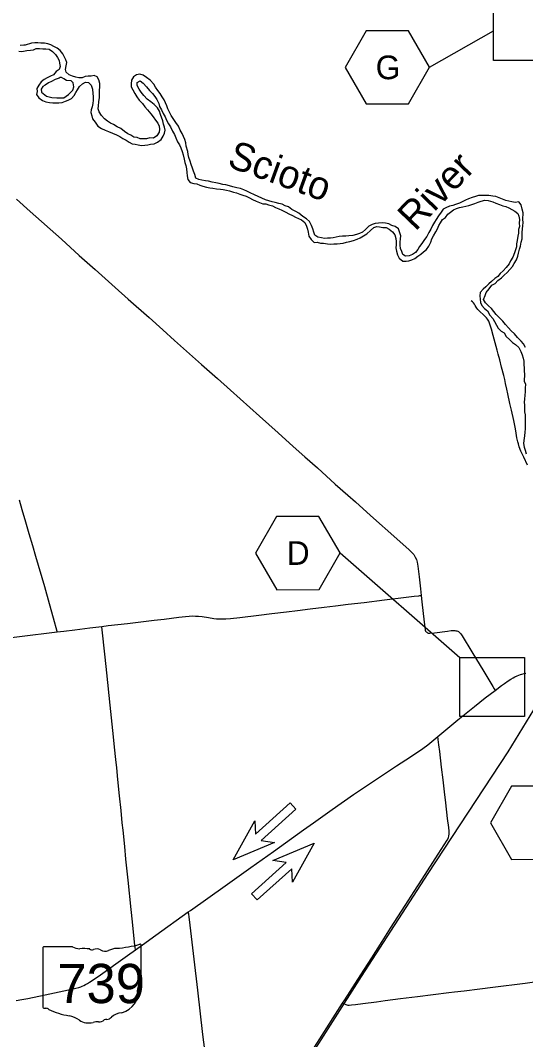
# Model space of a CAD drawing. Extents: x 0 to 680, y 0 to 440.
# Drawn here: x 332.1 to 391.8, y 219.2 to 339.7 of the extents above; entities that cross this region are included whole.
import ezdxf

# ---------------------------------------------------------------- set-up
doc = ezdxf.new("R2010")
doc.units = 0
for name, color, linetype in [('GM_X_County_Road', 7, 'Continuous'), ('GM_X_Major_River', 7, 'Continuous'), ('GM_X_Major_River_Text', 7, 'Continuous'), ('GM_X_State_Location', 7, 'Continuous'), ('GM_X_State_Route', 7, 'Continuous'), ('GM_X_State_Shield', 7, 'Continuous'), ('GM_X_Township_Road', 7, 'Continuous'), ('PM_P_Cells', 7, 'Continuous'), ('RD_X_RR_2', 7, 'Continuous'), ('SH_Border', 7, 'Continuous')]:
    doc.layers.add(name, color=color, linetype=linetype)

msp = doc.modelspace()

# ---------------------------------------------------------------- linework, layer by layer
at = {"layer": 'GM_X_County_Road'}
for points in [[(331.6, 318.59), (333.23, 317.12), (336.91, 313.84), (339.03, 311.94), (340.9, 310.27), (343.26, 308.15), (344.81, 306.76), (347.27, 304.58), (348.89, 303.12), (350.29, 301.89), (353.46, 299.04), (355.35, 297.37), (356.89, 295.98), (360.31, 292.91), (362.52, 290.95), (364.31, 289.34), (365.69, 288.1), (367.16, 286.79), (369.27, 284.89), (370.75, 283.58), (371.65, 282.79), (373.44, 281.18), (376.55, 278.42), (378.02, 277.11), (378.33, 276.8), (378.54, 276.54), (378.73, 276.25), (378.87, 275.95), (378.96, 275.64), (379.03, 275.17), (379.18, 273.9), (379.34, 272.49), (379.43, 271.7)], [(341.7, 268.05), (342.43, 268.14), (344.72, 268.41), (347.87, 268.79), (349.06, 268.92), (350.8, 269.15), (351.56, 269.24), (352, 269.27), (352.44, 269.29), (352.77, 269.28), (353.1, 269.26), (353.53, 269.21), (354.29, 269.1), (354.94, 268.99), (355.26, 268.95), (355.59, 268.93), (355.92, 268.93), (356.35, 268.94), (356.9, 268.98), (357.98, 269.11), (360.26, 269.39), (361.78, 269.58), (363.5, 269.78), (364.8, 269.94), (366.31, 270.12), (367.95, 270.32), (369.31, 270.48), (370.8, 270.67), (372.68, 270.89), (375.1, 271.2), (377.65, 271.51), (378.59, 271.62), (379.17, 271.68), (379.28, 271.69), (379.43, 271.7)], [(379.43, 271.7), (379.52, 270.96), (379.79, 268.57), (379.89, 267.7), (379.91, 267.6), (379.95, 267.5), (380.01, 267.42), (380.08, 267.35), (380.16, 267.3), (380.26, 267.27), (380.36, 267.26), (380.47, 267.25), (381.01, 267.31), (382.53, 267.49), (382.97, 267.55), (383.13, 267.56), (383.3, 267.56), (383.41, 267.56), (383.52, 267.54), (383.63, 267.52), (383.74, 267.48), (383.83, 267.43), (383.93, 267.36), (384.09, 267.21), (384.2, 267.07), (384.29, 266.94), (385.4, 265.05), (386.82, 262.72), (387.89, 260.93), (388.06, 260.66), (388.17, 260.48)], [(336.42, 267.4), (337.22, 267.5), (338.52, 267.66), (340.26, 267.88), (341.7, 268.05)], [(345.67, 229.81), (345.63, 230.09), (345.6, 230.32), (345.31, 233.09), (345.15, 234.55), (344.79, 238.04), (344.54, 240.53), (344.39, 242.02), (344.21, 243.93), (344.11, 244.8), (343.96, 246.26), (343.78, 248.02), (343.59, 249.96), (343.46, 251.34), (343.36, 252.3), (343.2, 253.77), (343.07, 254.97), (342.67, 258.75), (342.29, 262.56), (342.1, 264.41), (341.71, 268.01), (341.7, 268.05)], [(304.05, 263.53), (305.27, 263.68), (308.54, 264.07), (312.01, 264.5), (313.86, 264.72), (318.96, 265.32), (320.59, 265.52), (322.44, 265.74), (323.74, 265.89), (325.33, 266.07), (326.86, 266.25), (329.13, 266.52), (331.02, 266.75), (333.53, 267.05), (334.83, 267.21), (336.42, 267.4)]]:
    msp.add_lwpolyline(points, dxfattribs=at)
at = {"layer": 'GM_X_Major_River'}
for points in [[(332.64, 336.82), (332.47, 336.79), (332.05, 336.76)], [(339.71, 333.09), (339.35, 332.96), (338.99, 332.93), (338.62, 333.01), (338.24, 333.12), (337.83, 333.29), (337.49, 333.6), (337.39, 333.94), (337.49, 334.35), (337.55, 334.75), (337.44, 335.09), (337.23, 335.45), (337.09, 335.8), (336.78, 336.19), (336.41, 336.44), (336, 336.65), (335.66, 336.83), (335.31, 336.95), (334.9, 337.04), (334.49, 337.06), (334.12, 337.08), (333.77, 337.07), (333.38, 337.03), (332.64, 336.82)], [(332.83, 336.16), (333.26, 336.23), (333.61, 336.26), (333.95, 336.43), (334.32, 336.4), (334.72, 336.36), (335.09, 336.37), (335.45, 336.34), (335.86, 336.06), (336.22, 335.72), (336.47, 335.36), (336.65, 334.99), (336.7, 334.66), (336.77, 334.28), (336.66, 333.94), (336.3, 333.69), (335.96, 333.31), (335.62, 333.12), (335.23, 332.95), (334.86, 332.76), (334.52, 332.47), (334.26, 332.09), (334, 331.68), (334.05, 331.33), (333.99, 330.97), (334.26, 330.59), (334.68, 330.28), (335.09, 330.1), (335.51, 330.01), (335.9, 329.99), (336.25, 330), (336.62, 330), (337, 330.02), (337.38, 330.2), (337.73, 330.29), (338.09, 330.5), (338.41, 330.84), (338.63, 331.2), (338.82, 331.54), (339.06, 331.9), (339.4, 332.25), (339.75, 332.42), (340.1, 332.4), (340.44, 332.09), (340.59, 331.62), (340.63, 331.08), (340.65, 330.75), (340.65, 330.29), (340.61, 329.89), (340.53, 329.52), (340.42, 329.16), (340.41, 328.83), (340.5, 328.44), (340.6, 328.09), (340.9, 327.69), (341.22, 327.24), (341.67, 326.94), (342.07, 326.77), (342.48, 326.58), (342.94, 326.41), (343.41, 326.2), (343.8, 325.99), (344.17, 325.77), (344.56, 325.55), (344.93, 325.33), (345.29, 325.15), (345.63, 325.08), (345.98, 325.02), (346.36, 324.95), (346.77, 324.97), (347.12, 325.02), (347.45, 325.09), (347.88, 325.14), (348.27, 325.34), (348.69, 325.63), (348.95, 326.03), (349.11, 326.38), (349.16, 326.74), (349.1, 327.1), (348.97, 327.48), (348.9, 327.87), (348.64, 328.62), (348.49, 329), (348.26, 329.4), (347.86, 329.8), (347.47, 330.1), (347.06, 330.42), (346.66, 330.86), (346.33, 331.26), (346.12, 331.61), (345.85, 332.02), (345.87, 332.39), (346.21, 332.59), (346.58, 332.33), (346.98, 331.88), (347.31, 331.45), (347.67, 331.07), (347.97, 330.73), (348.18, 330.38), (348.41, 329.92), (348.51, 329.54)], [(331.87, 336.08), (332.23, 336.04), (332.64, 336.12), (332.83, 336.16)], [(336.19, 332.75), (335.76, 332.51), (335.4, 332.36), (334.99, 332.09), (334.72, 331.9), (334.52, 331.6), (334.57, 331.23), (335.14, 330.76), (335.78, 330.6), (336.39, 330.57), (337.19, 330.58), (337.74, 330.97), (338.26, 331.5), (338.4, 331.87), (338.31, 332.34), (338.05, 332.57), (337.53, 332.63), (337.21, 332.84), (336.92, 333), (336.76, 332.99), (336.66, 332.89)], [(336.66, 332.89), (336.19, 332.75)], [(359.23, 319.35), (358.83, 319.53), (358.47, 319.71), (358.09, 319.84), (357.63, 319.94), (357.17, 320.05), (356.76, 320.15), (356.35, 320.28), (356, 320.34), (355.54, 320.45), (355.18, 320.54), (354.74, 320.61), (354.3, 320.7), (353.93, 320.75), (353.52, 320.85), (353.16, 320.92), (352.81, 321.06), (352.68, 321.49), (352.54, 321.89), (352.41, 322.26), (352.25, 322.7), (352.12, 323.08), (351.99, 323.53), (351.91, 323.87), (351.86, 324.24), (351.66, 324.87), (351.6, 325.27), (351.5, 325.64), (351.34, 326.02), (351.19, 326.36), (350.94, 326.77), (350.74, 327.22), (350.42, 327.66), (350.2, 328.02), (349.89, 328.47), (349.67, 328.87), (349.48, 329.27), (349.37, 329.64), (349.22, 329.99), (349.04, 330.34), (348.84, 330.71), (348.6, 331.08), (348.32, 331.44), (348.03, 331.83), (347.82, 332.21), (347.42, 332.66), (346.96, 333), (346.59, 333.26), (346.18, 333.38), (345.77, 333.28), (345.43, 333.07), (345.21, 332.67), (345.15, 332.24), (345.17, 331.87), (345.36, 331.51), (345.61, 331.09), (345.82, 330.71), (346.12, 330.29), (346.5, 329.89), (346.77, 329.52), (347.1, 329.15), (347.47, 328.68), (347.76, 328.34), (348.03, 327.95), (348.29, 327.59), (348.45, 327.21), (348.51, 326.86), (348.48, 326.51), (348.18, 326.09), (347.79, 325.82), (347.37, 325.85), (346.95, 325.71), (346.59, 325.73), (346.24, 325.74), (345.87, 325.87), (345.49, 325.94), (345.12, 326.16), (344.76, 326.31), (344.35, 326.61), (343.92, 326.93), (343.5, 327.13), (343.07, 327.42), (342.7, 327.58), (342.35, 327.81), (342.01, 328.09), (341.67, 328.47), (341.37, 328.92), (341.27, 329.27), (341.29, 329.62), (341.35, 330.11), (341.4, 330.61), (341.43, 331.05), (341.41, 331.47), (341.46, 331.83), (341.45, 332.26), (341.35, 332.71), (341.12, 333.05), (340.77, 333.2), (340.43, 333.14), (340.08, 333.15), (339.71, 333.09)], [(348.51, 329.54), (348.75, 329.14), (348.94, 328.74), (349.16, 328.33), (349.35, 327.95), (349.57, 327.5), (349.79, 327.16), (350.03, 326.62), (350.27, 326.23), (350.42, 325.85), (350.64, 325.37), (350.85, 325.03), (351.03, 324.66), (351.19, 324.24), (351.31, 323.84), (351.41, 323.34), (351.48, 322.93), (351.63, 322.56), (351.68, 322.19), (351.75, 321.73), (351.77, 321.35), (351.86, 320.93), (352.12, 320.57), (352.57, 320.45), (352.91, 320.41), (353.28, 320.25), (353.63, 320.14), (354.04, 320.01), (354.45, 319.94), (354.81, 319.89), (355.25, 319.82), (355.7, 319.77), (356.04, 319.72), (356.43, 319.65), (356.79, 319.59), (357.25, 319.42), (357.61, 319.34), (357.99, 319.18), (358.37, 319.06), (358.75, 318.94), (359.14, 318.75), (359.51, 318.54), (359.92, 318.35), (360.32, 318.21), (360.7, 318.04), (361.06, 318.02), (361.4, 317.91), (361.85, 317.8), (362.21, 317.59), (362.59, 317.45), (362.98, 317.3), (363.44, 317.05), (363.79, 316.85), (364.24, 316.65), (364.59, 316.45), (364.93, 316.29), (365.29, 316.13), (365.69, 315.81), (365.86, 315.4), (366, 315.03), (366.06, 314.69), (366.16, 314.22), (366.41, 313.81), (366.79, 313.45), (367.15, 313.49), (367.52, 313.4), (367.9, 313.37), (368.34, 313.32), (368.7, 313.25), (369.1, 313.31), (369.5, 313.31), (369.86, 313.35), (370.2, 313.39), (370.59, 313.49), (370.99, 313.58), (371.43, 313.69), (371.88, 313.87), (372.22, 314.03), (372.6, 314.26), (373, 314.49), (373.42, 314.9), (373.83, 315.24), (374.18, 315.34), (374.52, 315.3), (374.89, 315.22), (375.29, 315.22), (375.66, 315.06), (376.04, 314.74), (376.3, 314.36), (376.44, 313.93), (376.48, 313.59), (376.46, 313.19), (376.42, 312.85), (376.5, 312.42), (376.64, 311.99), (376.83, 311.63), (377.26, 311.27), (377.64, 311.25), (377.98, 311.29), (378.32, 311.43), (378.68, 311.59)], [(391.46, 315.82), (391.45, 316.18), (391.46, 316.98), (391.36, 317.41), (391.26, 317.92), (390.96, 318.27), (390.52, 318.21), (390.14, 318.28), (389.78, 318.36), (389.44, 318.44), (389.03, 318.58), (388.64, 318.76), (388.26, 318.92), (387.89, 318.96), (387.44, 319.01), (386.99, 319.04), (386.56, 319.04), (386.21, 319.02), (385.84, 318.9), (385.46, 318.8), (385.01, 318.62), (384.65, 318.46), (384.27, 318.28), (383.94, 318.1), (383.49, 317.94), (383.16, 317.86), (382.77, 317.77), (382.36, 317.56), (382.02, 317.39), (381.78, 317.05), (381.48, 316.63), (381.2, 316.19), (381, 315.85), (380.78, 315.47), (380.55, 315.04), (380.33, 314.63), (380.11, 314.18), (379.83, 313.8), (379.49, 313.35), (379.23, 313), (379.03, 312.64), (378.74, 312.27), (378.39, 312.04), (378, 311.87), (377.59, 311.83), (377.25, 312.05), (377.13, 312.38), (376.99, 312.74), (376.96, 313.14), (376.95, 313.49), (376.99, 313.88), (377.01, 314.25), (376.89, 314.61), (376.75, 315.08), (376.35, 315.36), (375.96, 315.48), (375.59, 315.66), (375.23, 315.76), (374.8, 315.78), (374.38, 315.75), (373.98, 315.72), (373.63, 315.59), (373.26, 315.41), (372.85, 315.02), (372.5, 314.69), (372.15, 314.52), (371.77, 314.42), (371.36, 314.31), (370.88, 314.26), (370.51, 314.22), (370.14, 314.21), (369.75, 314.18), (369.37, 314.1), (369.03, 314.03), (368.7, 313.98), (368.35, 313.97), (367.99, 313.93), (367.63, 314), (367.22, 314.09), (366.88, 314.35), (366.73, 314.68), (366.63, 315.1), (366.46, 315.49), (366.24, 315.93), (365.86, 316.27), (365.45, 316.55), (364.98, 316.94), (364.62, 317.15), (364.16, 317.36), (363.74, 317.7), (363.37, 317.81), (362.99, 317.98), (362.59, 318.09), (362.17, 318.19), (361.82, 318.28), (361.41, 318.39), (361.03, 318.5), (360.59, 318.7), (360.18, 318.89), (359.75, 319.1), (359.23, 319.35)], [(378.68, 311.59), (379.04, 311.84), (379.38, 312.09), (379.72, 312.35), (380.05, 312.65), (380.34, 313.03), (380.55, 313.5), (380.7, 313.89), (380.9, 314.25), (381.14, 314.71), (381.36, 315.08), (381.51, 315.46), (381.7, 315.8), (381.93, 316.2), (382.32, 316.43), (382.57, 316.82), (382.91, 317.06), (383.24, 317.33), (383.61, 317.5), (383.94, 317.62), (384.35, 317.67), (384.69, 317.75), (385.06, 317.85), (385.41, 317.94), (385.76, 318.08), (386.17, 318.24), (386.51, 318.36), (386.94, 318.46), (387.33, 318.44), (387.9, 318.29), (388.25, 318.13), (388.68, 317.95), (389.07, 317.82), (389.43, 317.73), (389.78, 317.55), (390.15, 317.35), (390.49, 317.17), (390.86, 316.91), (390.95, 316.56), (391.04, 316.19), (390.99, 315.75), (391.04, 315.36), (390.94, 315.01), (390.92, 314.57), (390.86, 314.23), (390.76, 313.72), (390.71, 313.31), (390.68, 312.96), (390.57, 312.6), (390.47, 312.23), (390.26, 311.71), (389.99, 311.29), (389.81, 310.93), (389.49, 310.51), (389.11, 310.13), (388.76, 309.81), (388.48, 309.44), (388.13, 309.2), (387.75, 308.85), (387.41, 308.56), (387.07, 308.21), (386.74, 307.94), (386.4, 307.56), (386.36, 307.14), (386.4, 306.76), (386.43, 306.35), (386.6, 306.01), (386.91, 305.66), (387.28, 305.37), (387.55, 304.86), (387.9, 304.48), (388.11, 304.1), (388.32, 303.69), (388.54, 303.32), (388.86, 302.96), (389.22, 302.76), (389.49, 302.36), (389.86, 301.99), (390.2, 301.64), (390.57, 301.39), (390.95, 301.03), (391.21, 300.58), (391.35, 300.18), (391.49, 299.79), (391.55, 299.41), (391.57, 299.01), (391.61, 298.64), (391.61, 298.25), (391.63, 297.89), (391.61, 297.08), (391.74, 296.69), (391.71, 296.22), (391.73, 295.79), (391.69, 295.4), (391.63, 294.92), (391.61, 294.57), (391.63, 294.24), (391.63, 293.9), (391.65, 293.42), (391.73, 293.06), (391.71, 292.63)], [(391.77, 301.03), (391.5, 301.46), (391.25, 301.81), (390.82, 302.23), (390.47, 302.65), (390.07, 303.02), (389.73, 303.38), (389.41, 303.75), (389.06, 304.14), (388.65, 304.58), (388.28, 304.96), (388.02, 305.31), (387.72, 305.65), (387.38, 305.97), (387.04, 306.31), (386.81, 306.72), (386.98, 307.18), (387.09, 307.55), (387.47, 307.97), (387.78, 308.42), (388.17, 308.63), (388.48, 308.98), (388.9, 309.27), (389.24, 309.61), (389.59, 309.9), (390.21, 310.63), (390.43, 310.98), (390.71, 311.4), (390.86, 311.86), (390.94, 312.21), (391.06, 312.66), (391.16, 313.02), (391.25, 313.5), (391.35, 313.9), (391.38, 314.64), (391.4, 315.1), (391.45, 315.44), (391.46, 315.82)], [(391.71, 292.63), (391.71, 292.19), (391.73, 291.8), (391.71, 291.44), (391.69, 291.04), (391.63, 290.59), (391.55, 290.06), (391.51, 289.7), (391.58, 289.26), (391.7, 288.91), (391.84, 288.47)]]:
    msp.add_lwpolyline(points, dxfattribs=at)
at = {"layer": 'GM_X_State_Route'}
for p, q in [((380.43, 334.2), (387.96, 338.51)), ((369.86, 276.74), (384.01, 264.39))]:
    msp.add_line(p, q, dxfattribs=at)
for points in [[(377.92, 338.52), (372.92, 338.51), (370.43, 334.17), (372.94, 329.85), (377.94, 329.86), (380.43, 334.2)], [(367.34, 281.07), (362.34, 281.05), (359.86, 276.71), (362.37, 272.39), (367.37, 272.41), (369.86, 276.74)], [(395.09, 249.16), (390.09, 249.15), (387.6, 244.81), (390.12, 240.48), (395.12, 240.5), (397.6, 244.84)]]:
    msp.add_lwpolyline(points, close=True, dxfattribs=at)
msp.add_lwpolyline([(331.57, 223.78), (332.22, 223.9), (332.94, 224.04), (335.01, 224.47), (338.32, 225.18), (338.62, 225.26), (338.96, 225.35), (339.2, 225.43), (339.37, 225.5), (339.58, 225.59), (339.78, 225.69), (339.98, 225.81), (340.24, 225.97), (341.24, 226.65), (344.71, 229.12), (345.67, 229.81), (346.49, 230.39), (348.09, 231.54), (351.91, 234.27), (352.18, 234.46), (356.28, 237.37), (359.29, 239.52), (361.99, 241.43), (365.54, 243.98), (366.7, 244.8), (368.92, 246.39), (371.42, 248.16), (372.95, 249.21), (376.52, 251.54), (378.17, 252.62), (379.62, 253.6), (380.23, 254.06), (381.4, 255.04), (382.33, 255.81), (383.75, 257.01), (385.71, 258.59), (387, 259.59), (388.17, 260.48), (388.92, 261.05), (389.27, 261.3), (389.7, 261.6), (390.02, 261.8), (390.28, 261.96), (390.48, 262.07), (390.76, 262.2), (390.96, 262.28), (391.17, 262.36), (391.34, 262.41), (391.58, 262.48), (391.8, 262.52)], dxfattribs=at)
at = {"layer": 'GM_X_State_Shield'}
for p, q in [((346.33, 226.65), (346.33, 230.33)), ((334.73, 230.03), (334.73, 222.99)), ((338.24, 230.16), (334.84, 230.16)), ((346.33, 226.65), (346.33, 226.65))]:
    msp.add_line(p, q, dxfattribs=at)
for centre, major_axis, start_param, end_param in [((342.19, 239.76), (12.3, 0), 4.814394, 5.042369), ((346.2, 230.35), (0.129, 0), 6.141152, 7.989035), ((334.86, 230.05), (0.134, 0), 1.712693, 3.28349), ((339.05, 230.97), (1.3, 0), 4.042523, 4.731795), ((339.48, 226.2), (4.68, 0), 1.404758, 1.657858), ((340.54, 230.09), (0.376, 0), 3.836095, 5.185415), ((341.09, 229.27), (0.782, 0), 0.950623, 2.079405), ((342.1, 230.39), (0.941, 0), 4.081561, 5.145723), ((343.76, 228), (2.48, 0), 1.699011, 2.107814), ((346.79, 225.1), (0.873, 0), 2.387724, 3.262537), ((346.3, 226.38), (0.2, 0), 1.883978, 3.671073), ((345.03, 225.91), (1.2, 0), 5.934695, 6.695948), ((346.19, 226.63), (0.138, 0), 5.05454, 6.418171), ((342.88, 224.63), (3.08, 0), 5.101752, 6.440018), ((334.86, 222.98), (0.136, 0), 3.00124, 4.508301), ((334.88, 223.7), (1.03, 0), 4.665946, 4.897461), ((335.09, 222.58), (0.373, 0), 0.519207, 1.627899), ((339.8, 228.91), (8.88, 0), 4.195997, 4.488961), ((337.15, 219.83), (2.78, 0), 0.823519, 1.323587), ((344.18, 221.01), (1.69, 0), 1.647645, 2.488434), ((340.16, 222.55), (1.76, 0), 4.026481, 4.996735), ((341.18, 220.11), (1.45, 0), 1.495662, 1.94098), ((341.31, 222.02), (0.94, 0), 4.691044, 5.507374), ((342.16, 221.34), (0.265, 0), 1.147584, 2.315152), ((342.05, 222.31), (0.994, 0), 4.937069, 5.64225)]:
    msp.add_ellipse(centre, major_axis=major_axis, ratio=0.8, start_param=start_param, end_param=end_param, dxfattribs=at)
at = {"layer": 'GM_X_Township_Road'}
for points in [[(392.01, 287.11), (391.54, 288.09), (391.21, 288.78), (391.01, 289.29), (390.91, 289.66), (390.85, 289.88), (390.75, 290.36), (390.66, 290.91), (390.57, 291.44), (390.38, 292.4), (390.1, 293.63), (389.92, 294.41), (389.68, 295.55), (389.56, 296.13), (389.41, 296.79), (389.3, 297.27), (389.18, 297.74), (388.92, 298.73), (388.71, 299.58), (388.52, 300.24), (388.39, 300.74), (387.93, 302.46), (387.73, 303.2), (387.54, 303.82), (387.41, 304.16), (387.34, 304.27), (387.26, 304.39), (387.16, 304.54), (387.04, 304.68), (386.85, 304.86), (386.32, 305.34), (386.13, 305.55), (386.01, 305.7), (385.93, 305.82), (385.81, 306.02), (385.73, 306.15), (385.6, 306.33), (385.5, 306.43), (385.32, 306.57)], [(336.42, 267.4), (336.4, 267.46), (335.96, 269.02), (335.5, 270.72), (334.95, 272.72), (333.9, 276.32), (333.54, 277.57), (333.12, 279.01), (332.71, 280.38), (332.28, 281.84), (331.96, 283)], [(370.13, 223.47), (370.4, 223.89), (372.29, 226.83), (373.59, 228.85), (374.82, 230.79), (375.82, 232.36), (377.54, 235.02), (378.6, 236.68), (379.53, 238.16), (381.43, 241.1), (382.48, 242.76), (382.64, 243.06), (382.71, 243.27), (382.74, 243.49), (382.75, 243.6), (382.75, 243.71), (382.74, 243.83), (382.69, 244.26), (382.55, 245.34), (382.33, 247.19), (382.17, 248.49), (382.01, 249.9), (381.84, 251.42), (381.62, 253.27), (381.53, 254.05), (381.45, 254.68), (381.4, 255.04)], [(354.17, 215.56), (353.64, 219.79), (353.03, 225.01), (352.6, 228.7), (352.12, 232.72), (352.01, 233.71), (351.96, 234.01), (351.91, 234.27)], [(370.13, 223.47), (370.32, 223.4), (370.54, 223.32), (370.66, 223.28), (370.77, 223.26), (370.9, 223.25), (371.19, 223.27), (371.65, 223.33), (372.53, 223.45), (374.15, 223.65), (375.16, 223.79), (376.98, 224.02), (379, 224.27), (382.68, 224.74), (383.38, 224.82), (384.52, 224.95), (386.37, 225.18), (387.89, 225.37), (391.7, 225.86), (394.5, 226.23)], [(361.66, 210.13), (363.29, 212.73), (365.29, 215.87), (367.45, 219.28), (370.13, 223.47)]]:
    msp.add_lwpolyline(points, dxfattribs=at)
at = {"layer": 'PM_P_Cells'}
for p, q in [((359.85, 243.48), (363.93, 247.17)), ((363.93, 247.17), (364.6, 246.42)), ((364.6, 246.42), (360.52, 242.74)), ((364.27, 246.79), (364.27, 246.79)), ((357.22, 240.43), (359.77, 245.07)), ((359.77, 245.07), (359.85, 243.48)), ((362.09, 242.49), (357.22, 240.43)), ((360.52, 242.74), (362.09, 242.49)), ((361.89, 240.36), (366.77, 242.42)), ((366.77, 242.42), (364.22, 237.78)), ((366.77, 242.42), (366.77, 242.42)), ((357.22, 240.43), (357.22, 240.43)), ((359.38, 236.43), (363.46, 240.11)), ((363.46, 240.11), (361.89, 240.36)), ((364.13, 239.37), (360.05, 235.69)), ((364.22, 237.78), (364.13, 239.37)), ((360.05, 235.69), (359.38, 236.43)), ((359.71, 236.06), (359.71, 236.06))]:
    msp.add_line(p, q, dxfattribs=at)
at = {"layer": 'RD_X_RR_2'}
msp.add_lwpolyline([(365.59, 215.99), (372.38, 226.62), (380.24, 238.84), (389.71, 253.22), (394.05, 260.33), (395.78, 262.86), (396.55, 263.77), (397.21, 264.65), (398.06, 265.64), (400.09, 267.7), (402.5, 269.94), (406.01, 273.47), (412.05, 279.3), (417.6, 284.61), (426.57, 293.35), (435.6, 302.17), (441.57, 308.08), (456.14, 322.29), (463.88, 329.73), (466.92, 332.72)], dxfattribs=at)
at = {"layer": 'SH_Border'}
for points in [[(387.96, 342.01), (395.58, 342.01), (395.58, 335.01), (387.96, 335.01)], [(384.01, 264.39), (391.63, 264.39), (391.63, 257.39), (384.01, 257.39)]]:
    msp.add_lwpolyline(points, close=True, dxfattribs=at)

# ---------------------------------------------------------------- texts
at = {"layer": 'GM_X_Major_River_Text'}
for s, rotation, p in [('Scioto', 340.0119, (356.37, 322.49)), ('River', 46.0271, (378.73, 314.69))]:
    msp.add_text(s, height=3.334, rotation=rotation, dxfattribs=at).set_placement(p)
at = {"layer": 'GM_X_State_Location'}
msp.add_text('739', height=0.00667, rotation=0, dxfattribs=at).set_placement((338.04, 225.56))
for s in ['s', 'r']:
    msp.add_text(s, height=0.00667, dxfattribs=at).set_placement((340.4, 226.04))
at = {"layer": 'GM_X_State_Route'}
for s, p in [('G', (374.05, 332.78)), ('D', (363.54, 275.33))]:
    msp.add_text(s, height=2.8, dxfattribs=at).set_placement(p)
at = {"layer": 'GM_X_State_Shield'}
msp.add_text('739', height=4.641, dxfattribs=at).set_placement((336.43, 223.49))

doc.saveas('drawing.dxf')
